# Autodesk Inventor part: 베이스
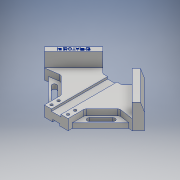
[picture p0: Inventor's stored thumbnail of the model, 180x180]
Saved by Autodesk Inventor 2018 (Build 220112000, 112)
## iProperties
Created: 2020-05
Part Number: 베이스
Material: 알루미늄 6061
Document SubType Name: Modeling
Designer: Administrator
Density: 2.7 g/cm^3
Appearance: 알루미늄 - 평지
Author: Administrator
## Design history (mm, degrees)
sketch "스케치1"
  geometry: L1 (0, 84.853)-(-84.853, 0); L2 (-84.853, 0)-(0, -84.853); L3 (0, -84.853)-(84.853, 0); L4 (84.853, 0)-(0, 84.853); 1 further point
  constraints: 8 end point, 2 horizontal alignment, 2 vertical alignment, 1 point on line
  dimensions: "d0" = 120 distance of L1.start L1.end; "d1" = 120 distance of L1.end L2.end; "d2" = 120 distance of L2.end L3.end; "d3" = 120 distance of L3.end L4.end; "d4" = 90 deg angle of L2 L1
extrude "돌출1" new body sketch "스케치1" stored distance "d5" = 42; taper "d6" = 0 deg
node "스케치2"
sketch "스케치3"
  geometry: L1 (0, 84.853)-(-84.853, 0) reference; L2 (84.853, 0)-(0, 84.853) reference; L3 (-74.246, -10.607)-(0, 63.64); L4 (0, 63.64)-(74.246, -10.607); L5 (-84.853, 0)-(0, -84.853) reference; L6 (0, -84.853)-(84.853, 0) reference; 1 further point
  constraints: 4 end point, 1 other
  dimensions: "d7" = 15 distance between parallel lines of L1 L3
extrude "돌출2" cut sketch "스케치3" distance "d8" = 24; taper "d9" = 0 deg
sketch "스케치4"
  geometry: L1 (-16.005, 30.147)-(-35.355, 49.497); L2 (0, 84.853)-(-84.853, 0) reference; L3 (35.355, 49.497)-(16.005, 30.147); L4 (84.853, 0)-(0, 84.853) reference; L5 (0, -84.853)-(-84.853, 0) reference; L6 (0, 30.147)-(16.005, 30.147); L7 (16.005, 30.147)-(-16.005, 30.147); 1 further point
  constraints: 8 end point, 1 parallel
  dimensions: "d11" = 50 distance between parallel lines of L2 L3; "d13" = 115 distance of L5.start L6.start
extrude "돌출3" cut sketch "스케치4" distance "d14" = 42; taper "d15" = 0 deg
sketch "스케치5"
  geometry: L1 (0, -84.853)-(-74.246, -10.607) reference; L2 (-20, -36.569)-(-49.497, -7.071); L3 (-35.355, 49.497)-(-84.853, 0) reference; L4 (-49.497, -7.071)-(-74.246, -10.607); L5 (-20, -64.853)-(-20, -36.569); 1 further point
  constraints: 6 end point, 1 parallel, 1 point on line, 1 vertical
  dimensions: "d16" = 20 distance between parallel lines of L1 L2
extrude "돌출4" cut sketch "스케치5" distance "d19" = 10; taper "d20" = 0 deg
sketch "스케치6"
  geometry: L1 (-20, -64.853)-(-74.246, -10.607) reference; L2 (-20, -57.782)-(-68.059, -9.723); L3 (-74.246, -10.607)-(-49.497, -7.071) reference; L4 (-20, -36.569)-(-20, -64.853) reference; 1 further point
  constraints: 2 end point, 2 point on line, 1 parallel
  dimensions: "d21" = 5 distance between parallel lines of L1 L2
extrude "돌출5" cut sketch "스케치6" distance "d22" = 10; taper "d23" = 0 deg
sketch "스케치7"
  geometry: L1 (0, -84.853)-(-20, -64.853) reference; L2 (-20, -64.853)-(20, -64.853); L3 (74.246, -10.607)-(0, -84.853) reference; 1 further point
  constraints: 2 end point, 1 horizontal, 1 point on line
extrude "돌출6" cut sketch "스케치7" distance "d24" = 42; taper "d25" = 0 deg
sketch "스케치8"
  geometry: L1 (-68.059, -9.723)-(-20, -57.782) reference; L2 (-74.246, -10.607)-(-20, -64.853); L3 (-35.355, 49.497)-(-84.853, 0) reference; L4 (-52.326, -21.213)-(-32.527, -41.012); L5 (-46.669, -15.556)-(-26.87, -35.355); A1 r 4 centre (-49.497, -18.385) between (-46.669, -15.556) and (-52.326, -21.213); A2 r 4 centre (-29.698, -38.184) between (-32.527, -41.012) and (-26.87, -35.355); 1 further point
  constraints: 6 end point, 4 point on circle, 2 centre point
  dimensions: "d29" = 8 diameter of A1; "d30" = 8 diameter of A2
extrude "돌출7" cut sketch "스케치8" distance "d31" = 42; taper "d32" = 0 deg
sketch "스케치9"
  geometry: L1 (-20, -64.853)-(20, -64.853) reference; C1 r 2.25 at (-14, -46.853); C2 r 2.25 at (-14, -58.853); C3 r 2.25 at (14, -46.853); C4 r 2.25 at (14, -58.853); 1 further point
  constraints: 4 centre point
  dimensions: "d37" = 4.5 diameter of C1; "d38" = 4.5 diameter of C2; "d39" = 4.5 diameter of C3; "d40" = 4.5 diameter of C4
extrude "돌출8" cut sketch "스케치9" distance "d41" = 42; taper "d42" = 0 deg
sketch "스케치10"
  geometry: L1 (-8, 30.147)-(-8, -65.204); L2 (8, 30.147)-(8, -65.204); L3 (-8, 30.147)-(8, 30.147); L4 (16.005, 30.147)-(-16.005, 30.147) reference; L5 (-8, -65.204)-(8, -65.204); L6 (-20, -64.853)-(20, -64.853) reference; 1 further point
  constraints: 8 end point, 1 collinear, 1 parallel
extrude "돌출9" cut sketch "스케치10" distance "d45" = 3.5; taper "d46" = 0 deg
sketch "스케치11"
  geometry: L1 (40, 0)-(0, 0) reference; L2 (26, 3.5)-(14, 3.5); L3 (14, 0)-(14, 3.5); L4 (26, 0)-(26, 3.5); L5 (14, 0)-(26, 0); 1 further point
  constraints: 8 end point, 2 parallel, 1 collinear
  dimensions: "d47" = 3.5 distance between parallel lines of L1 L2; "d49" = 12 distance between parallel lines of L3 L4
extrude "돌출10" cut sketch "스케치11" distance "d50" = 151; taper "d51" = 0 deg
sketch "스케치12"
  geometry: C1 r 2.25 at (14, -58.853) reference; C2 r 4 at (14, -58.853); C3 r 2.25 at (14, -46.853) reference; C4 r 4 at (14, -46.853); C5 r 2.25 at (-14, -58.853) reference; C6 r 4 at (-14, -58.853); C7 r 2.25 at (-14, -46.853) reference; C8 r 4 at (-14, -46.853); 1 further point
  constraints: 4 centre point, 4 coincident
  dimensions: "d52" = 8 diameter of C2; "d53" = 8 diameter of C4; "d54" = 8 diameter of C6; "d55" = 8 diameter of C8
extrude "돌출11" cut sketch "스케치12" distance "d56" = 10; taper "d57" = 0 deg
fillet "모깎기1" dims "d58" = 5
sketch "스케치13"
  geometry: L1 (0, 15)-(-5, 0); L2 (-5, 0)-(0, 0); L3 (0, 0)-(0, 15); 1 further point
  constraints: 6 end point, 1 perpendicular
extrude "돌출12" cut sketch "스케치13" distance "d61" = 100; taper "d62" = 0 deg
sketch "스케치14"
  geometry: L1 (-24.749, 38.891)-(-74.246, -10.607); L2 (-74.246, -10.607)-(-81.317, -3.536); L3 (-81.317, -3.536)-(-31.82, 45.962); L4 (-31.82, 45.962)-(-24.749, 38.891); L5 (-24.749, 38.891)-(-31.82, 45.962) reference; L6 (-81.317, -3.536)-(-74.246, -10.607) reference; 1 further point
  constraints: 2 coincident, 2 other
feature "엠보싱1" sketch "스케치14" dims "d0" = 120, "d1" = 120, "d2" = 120, "d3" = 120, "d4" = 90 deg, "d63" = 0.5, "d64" = 0
node "솔리드1"
mirror "미러1"
mirror "미러2"
